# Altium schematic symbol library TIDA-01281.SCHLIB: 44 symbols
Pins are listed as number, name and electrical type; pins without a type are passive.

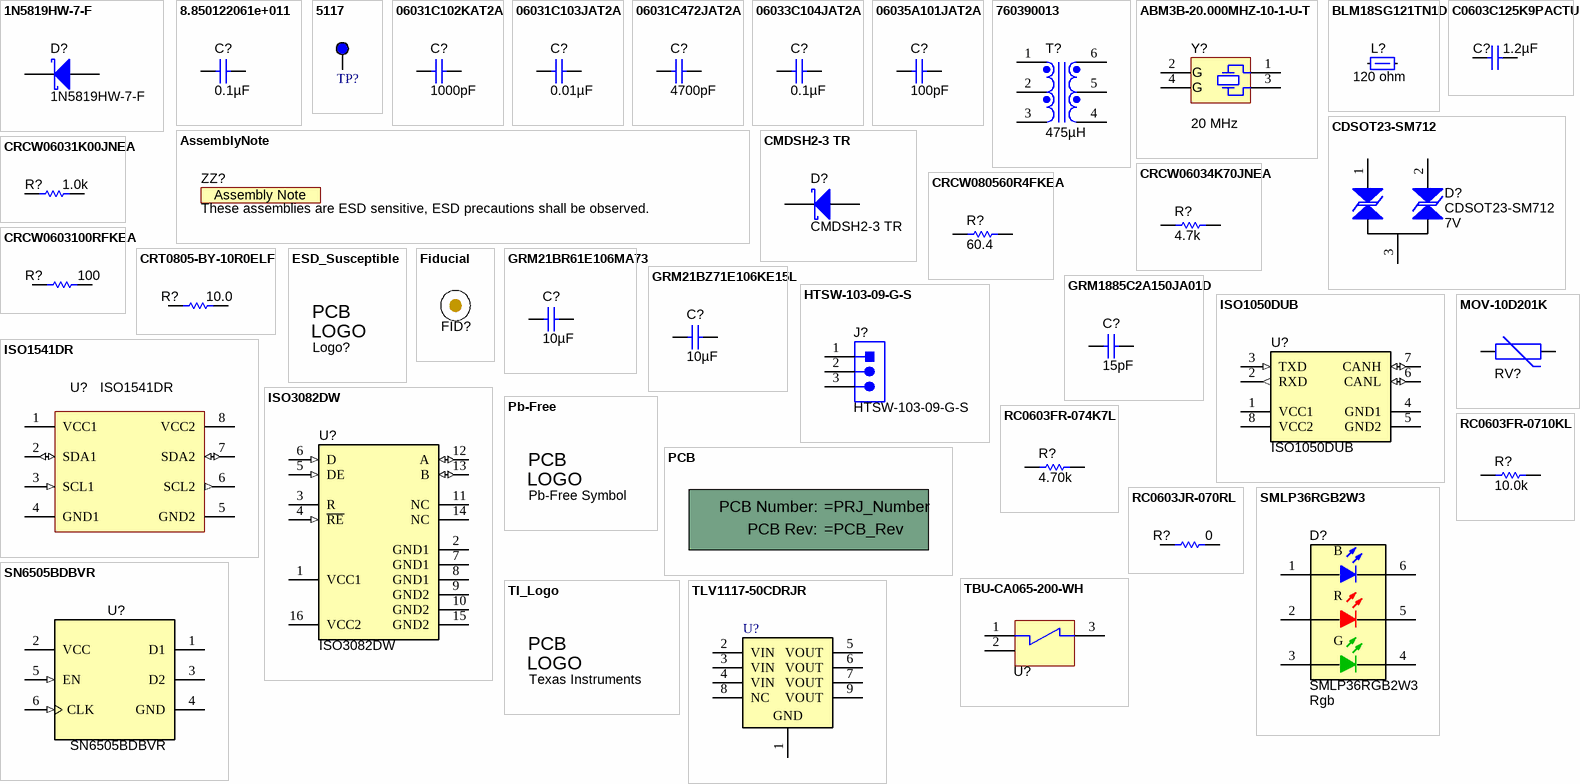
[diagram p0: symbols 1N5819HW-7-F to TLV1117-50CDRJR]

## 1N5819HW-7-F
designator D?
Diode, Schottky, 40 V, 1 A, SOD-123; Manufacturer: Diodes Inc.; U/M: EA; Vf_V: 0.45; Value: 40V; Value1: 1A; Value2: 0.45V; Io_A: 1; Vr_V: 40; TJmax_C: 125; SizeAreaWB_mm2: 13.095; SizeArea_mm2: 6.545; SizeX_mm: 3.85; SizeY_mm: 1.7; SizeZ_mm: 1.35; AEC Category: Q101
signal-integrity model Diode
simulation model DI_1N5819HW
footprint SOD-123
pins: 1 K, 2 A

## 8.850122061e+011
designator C?  ValueDisplayed: 0.1µF  (hidden comment: 8.850122061e+011)
CAP, CERM, 0.1 µF, 50 V, +/- 10%, X7R, 0603; Manufacturer: Wurth Elektronik; Polarized: N; CompType: Capacitor; Value: 0.1uF; U/M: EA; Cap_F: 0.0000001; Tolerance_%: 10; Value1: Unknown; VDC_V: 50; Value2: 50V; TaMin_C: -55; TaMax_C: 125; Cap_Case: 0603; SizeArea_mm2: 1.28; SizeAreaWB_mm2: 4.68; SizeX_mm: 1.6; SizeY_mm: 0.8; SizeZ_mm: 1; AEC Category: Q200
signal-integrity model Cap
simulation model Cap
footprint 0603
footprint 0603M
footprint 0603L
footprint 0603_HV
footprint 0603S
pins: 1, 2

## 5117
designator TP?  (value not drawn)
Test Point, Miniature, Blue, TH; Manufacturer: Keystone; CompType: Test Point Loop; U/M: EA; ContactFinish: Silver
footprint Keystone5117
pins: 1

## 06031C102KAT2A
designator C?  ValueDisplayed: 1000pF  (hidden comment: 06031C102KAT2A)
CAP, CERM, 1000 pF, 100 V, +/- 10%, X7R, 0603; Manufacturer: AVX; Polarized: N; CompType: Capacitor; Value: 1000pF; U/M: EA; Cap_F: 0.000000001; Tolerance_%: 10; ESR_ohm: 0.276; Value1: 0.276 ohm; VDC_V: 100; Value2: 100V; TaMin_C: -55; TaMax_C: 125; Cap_Case: 0603
signal-integrity model Cap
simulation model Cap
footprint 0603
footprint 0603M
footprint 0603L
footprint 0603_HV
footprint 0603S
pins: 1, 2

## 06031C103JAT2A
designator C?  ValueDisplayed: 0.01µF  (hidden comment: 06031C103JAT2A)
CAP, CERM, 0.01 µF, 100 V, +/- 5%, X7R, 0603; Manufacturer: AVX; Polarized: N; CompType: Capacitor; Value: 0.01uF; U/M: EA; Cap_F: 0.00000001; Tolerance_%: 5; ESR_ohm: 0.098; Value1: 0.098 ohm; VDC_V: 100; Value2: 100V; TaMin_C: -55; TaMax_C: 125; Cap_Case: 0603
signal-integrity model Cap
simulation model Cap
footprint 0603
footprint 0603M
footprint 0603L
footprint 0603_HV
footprint 0603S
pins: 1, 2

## 06031C472JAT2A
designator C?  ValueDisplayed: 4700pF  (hidden comment: 06031C472JAT2A)
CAP, CERM, 4700 pF, 100 V, +/- 5%, X7R, 0603; Manufacturer: AVX; Polarized: N; CompType: Capacitor; Value: 4700pF; U/M: EA; Cap_F: 0.0000000047; Tolerance_%: 5; ESR_ohm: 0.136; Value1: 0.136 ohm; VDC_V: 100; Value2: 100V; TaMin_C: -55; TaMax_C: 125; Cap_Case: 0603; SizeArea_mm2: 1.28; SizeAreaWB_mm2: 4.68; SizeX_mm: 1.6; SizeY_mm: 0.8; SizeZ_mm: 1; AEC Category: Q200
signal-integrity model Cap
simulation model Cap
footprint 0603
footprint 0603M
footprint 0603L
footprint 0603_HV
footprint 0603S
pins: 1, 2

## 06033C104JAT2A
designator C?  ValueDisplayed: 0.1µF  (hidden comment: 06033C104JAT2A)
CAP, CERM, 0.1 µF, 25 V, +/- 5%, X7R, 0603; Manufacturer: AVX; Polarized: N; CompType: Capacitor; Value: 0.1uF; U/M: EA; Cap_F: 0.0000001; Tolerance_%: 5; ESR_ohm: 0.05; Value1: 0.05 ohm; VDC_V: 25; Value2: 25V; TaMin_C: -55; TaMax_C: 125; Cap_Case: 0603
signal-integrity model Cap
simulation model Cap
footprint 0603
footprint 0603M
footprint 0603L
footprint 0603_HV
footprint 0603S
pins: 1, 2

## 06035A101JAT2A
designator C?  ValueDisplayed: 100pF  (hidden comment: 06035A101JAT2A)
CAP, CERM, 100 pF, 50 V, +/- 5%, C0G/NP0, 0603; Manufacturer: AVX; Polarized: N; CompType: Capacitor; Value: 100pF; U/M: EA; Cap_F: 0.0000000001; Tolerance_%: 5; ESR_ohm: 0.119; Value1: 0.119 ohm; VDC_V: 50; Value2: 50V; TaMin_C: -55; TaMax_C: 125; Cap_Case: 0603; SizeArea_mm2: 1.28; SizeAreaWB_mm2: 4.68; SizeX_mm: 1.6; SizeY_mm: 0.8; SizeZ_mm: 1; AEC Category: Q200
signal-integrity model Cap
simulation model Cap
footprint 0603
footprint 0603M
footprint 0603L
footprint 0603_HV
footprint 0603S
pins: 1, 2

## 760390013
designator T?  ValueDisplayed: 475µH  (hidden comment: 760390013)
Transformer, 475 uH, SMT; Manufacturer: Wurth Elektronik; SymbolCreator: a0799628; Value: 475uH; Lp: 475; DCR_ohm: 0.32
footprint Wurth_760390013
pins: 1, 2, 3, 4, 5, 6

## ABM3B-20.000MHZ-10-1-U-T
designator Y?  Frequency: 20 MHz  (hidden comment: ABM3B-20.000MHZ-10-1-U-T)
Crystal, 20 MHz, 10 pF, SMD; Manufacturer: Abracon Corportation; SymbolCreator: a0412235; U/M: EA; TaMin_C: -10; TaMax_C: 60; Frequency Stability: ±10ppm
footprint ABRACON_ABM3B
pins: 1, 2 GND (power), 3, 4 GND (power)

## AssemblyNote
designator ZZ?, comment These assemblies are ESD sensitive, ESD precautions shall be observed.  (no BOM)
SymbolCreator: codlsc; CompType: AssemblyNote
footprint AssemblyNote

## BLM18SG121TN1D
designator L?  value 120 ohm  (hidden comment: BLM18SG121TN1D)
Ferrite Bead, 120 ohm @ 100 MHz, 3 A, 0603; Manufacturer: MuRata; Imax_A: 3; DCR_ohm: 0.025; Value1: 0.025 ohm; Value2: 3A; ZTyp@100MHz_Ohm: 120
footprint 0603
footprint 0603M
footprint 0603L
footprint 0603_HV
footprint 0603S
pins: 1, 2

## C0603C125K9PACTU
designator C?  ValueDisplayed: 1.2µF  (hidden comment: C0603C125K9PACTU)
CAP, CERM, 1.2 µF, 6.3 V, +/- 10%, X5R, 0603; Manufacturer: Kemet; Polarized: N; CompType: Capacitor; Value: 1.2uF; U/M: EA; Cap_F: 0.0000012; Tolerance_%: 10; Value1: Unknown; VDC_V: 6.3; Value2: 6.3V; TaMin_C: -55; TaMax_C: 85; Cap_Case: 0603
signal-integrity model Cap
simulation model Cap
footprint 0603
footprint 0603M
footprint 0603L
footprint 0603_HV
footprint 0603S
pins: 1, 2

## CDSOT23-SM712
designator D?  value 7V
Diode, TVS, Bi, 7 V, 400 W, SOT-23; Manufacturer: Bourns; SymbolCreator: a0411947; U/M: EA; Power_W: 400; Vr_V: 7; Value1: 400W
footprint SOT-23
footprint SOT-23M
footprint SOT-23L
pins: 1, 2, 3

## CMDSH2-3 TR
designator D?
Diode, Schottky, 30 V, 0.2 A, SOD-323; Manufacturer: Central Semiconductor; U/M: EA; Vf_V: 0.55; Value: 30V; Value1: 0.2A; Value2: 0.55V; Io_A: 0.2; Vr_V: 30; TJmax_C: 150; SizeAreaWB_mm2: 8.695; SizeArea_mm2: 3.645; SizeX_mm: 2.7; SizeY_mm: 1.35; SizeZ_mm: 1; AEC Category: Q101
signal-integrity model Diode
footprint SOD-323
pins: 1 K, 2 A

## CRCW06031K00JNEA
designator R?  ValueDisplayed: 1.0k  (hidden comment: CRCW06031K00JNEA)
RES, 1.0 k, 5%, 0.1 W, 0603; Manufacturer: Vishay-Dale; CompType: Resistor; Value: 1.0k; Res_ohm: 1000; Value_Code: 1k00; Tolerance_%: 5; Power_W: 0.1; Value2: 0.1W; VDC_V: 75; TempCo: 200 ppm/C; EIA_Code: E24; U/M: EA
signal-integrity model Resistor
simulation model Resistor
footprint 0603
footprint 0603M
footprint 0603L
footprint 0603_HV
footprint 0603S
pins: 1, 2

## CRCW06034K70JNEA
designator R?  ValueDisplayed: 4.7k  (hidden comment: CRCW06034K70JNEA)
RES, 4.7 k, 5%, 0.1 W, 0603; Manufacturer: Vishay-Dale; CompType: Resistor; Value: 4.7k; Res_ohm: 4700; Value_Code: 4k70; Tolerance_%: 5; Power_W: 0.1; Value2: 0.1W; VDC_V: 75; TempCo: 200 ppm/C; SizeArea_mm2: 1.28; SizeX_mm: 1.6; SizeY_mm: 0.8; SizeZ_mm: 1; EIA_Code: E24; U/M: EA; AEC Category: Q200
signal-integrity model Resistor
simulation model Resistor
footprint 0603
footprint 0603M
footprint 0603L
footprint 0603_HV
footprint 0603S
pins: 1, 2

## CRCW080560R4FKEA
designator R?  ValueDisplayed: 60.4  (hidden comment: CRCW080560R4FKEA)
RES, 60.4, 1%, 0.125 W, 0805; Manufacturer: Vishay-Dale; CompType: Resistor; Value: 60.4; Value_Code: 60R4; Tolerance_%: 1; Power_W: 0.125; Value2: 0.125W; VDC_V: 150; TempCo: 100 ppm/C; EIA_Code: E96; U/M: EA; AEC Category: Q200
signal-integrity model Resistor
simulation model Resistor
footprint 0805_HV
footprint 0805_HV1
footprint 0805
footprint 0805M
pins: 1, 2

## CRCW0603100RFKEA
designator R?  ValueDisplayed: 100  (hidden comment: CRCW0603100RFKEA)
RES, 100, 1%, 0.1 W, 0603; Manufacturer: Vishay-Dale; CompType: Resistor; Value: 100; Value_Code: 100R; Tolerance_%: 1; Power_W: 0.1; Value2: 0.1W; VDC_V: 75; TempCo: 100 ppm/C; EIA_Code: E96; U/M: EA
signal-integrity model Resistor
simulation model Resistor
footprint 0603
footprint 0603M
footprint 0603L
footprint 0603_HV
footprint 0603S
pins: 1, 2

## CRT0805-BY-10R0ELF
designator R?  ValueDisplayed: 10.0  (hidden comment: CRT0805-BY-10R0ELF)
RES, 10.0, 0.1%, 0.1 W, 0805; Manufacturer: Bourns; CompType: Resistor; Value: 10.0; Res_ohm: 10; Value_Code: 10R0; Tolerance_%: 0.1; Value2: 0.1W; VDC_V: 100; TempCo: 25 ppm/C; EIA_Code: E192; U/M: EA
signal-integrity model Resistor
simulation model Resistor
footprint 0805_HV
footprint 0805_HV1
footprint 0805
footprint 0805M
pins: 1, 2

## ESD_Susceptible
designator Logo?, comment ESD Susceptible  (value not drawn)  (no BOM)
ESD Susceptible Symbol; SymbolCreator: a0412235
footprint ESD_Overlay_Large
footprint ESD_Overlay_Medium
footprint ESD_Overlay_Small

## Fiducial
designator FID?  (value not drawn)
Fiducial mark.  There is nothing to buy or mount.; SymbolCreator: codlsc
footprint Fiducial10-30
footprint Fiducial10-20
footprint Fiducial15-30
footprint Fiducial20-40
footprint Fiducial6.4-20

## GRM21BR61E106MA73
designator C?  ValueDisplayed: 10µF  (hidden comment: GRM21BR61E106MA73)
CAP, CERM, 10 µF, 25 V, +/- 20%, X5R, 0805; Manufacturer: MuRata; Polarized: N; CompType: Capacitor; Value: 10uF; U/M: EA; Cap_F: 0.00001; Tolerance_%: 20; Value1: Unknown; VDC_V: 25; Value2: 25V; TaMin_C: -55; TaMax_C: 85; Cap_Case: 0805; SizeArea_mm2: 2.5; SizeAreaWB_mm2: 6.75; SizeX_mm: 2; SizeY_mm: 1.25; SizeZ_mm: 1.45; AEC Category: Q200
signal-integrity model Cap
simulation model Cap
footprint 0805_HV
footprint 0805_HV1
footprint 0805
footprint 0805M
footprint 0805L
pins: 1, 2

## GRM21BZ71E106KE15L
designator C?  ValueDisplayed: 10µF  (hidden comment: GRM21BZ71E106KE15L)
CAP, CERM, 10 µF, 25 V, +/- 10%, X7R, 0805; Manufacturer: MuRata; Polarized: N; CompType: Capacitor; Value: 10uF; U/M: EA; Cap_F: 0.00001; Tolerance_%: 10; Value1: Unknown; VDC_V: 25; Value2: 25V; TaMin_C: -55; TaMax_C: 125; Cap_Case: 0805; SizeArea_mm2: 2.5; SizeAreaWB_mm2: 6.75; SizeX_mm: 2; SizeY_mm: 1.25; SizeZ_mm: 1.45; AEC Category: Q200
signal-integrity model Cap
simulation model Cap
footprint 0805_HV
footprint 0805_HV1
footprint 0805
footprint 0805M
footprint 0805L
pins: 1, 2

## GRM1885C2A150JA01D
designator C?  ValueDisplayed: 15pF  (hidden comment: GRM1885C2A150JA01D)
CAP, CERM, 15 pF, 100 V, +/- 5%, C0G/NP0, 0603; Manufacturer: MuRata; Polarized: N; CompType: Capacitor; Value: 15pF; U/M: EA; Cap_F: 0.000000000015; Tolerance_%: 5; Value1: Unknown; VDC_V: 100; Value2: 100V; TaMin_C: -55; TaMax_C: 125; Cap_Case: 0603
signal-integrity model Cap
simulation model Cap
footprint 0603
footprint 0603M
footprint 0603L
footprint 0603_HV
footprint 0603S
pins: 1, 2

## HTSW-103-09-G-S
designator J?
Header, 100mil, 3x1, Gold, TH; Manufacturer: Samtec; SymbolCreator: a0799628; Pitch_mm: 2.54; Gender: Male; Row_Count: 1; Cert_CSA: Y
footprint Samtec_HTSW-103-09-x-S
pins: 1, 2, 3
3 alternate drawings of the same symbol

## ISO1050DUB
designator U?
Isolated CAN Transceiver, -55 to 105 degC, 8-pin SOP (DUB), Green (RoHS & no Sb/Br); Manufacturer: Texas Instruments; Alternate PartNumber: Equivalent; Drivers Per Package: 1; Isolated: Yes; Rating: Catalog
footprint DUB0008A_N (SOP, 8-Leads, Body 9.5x6.62mm, Pitch 2.54mm, IPC Medium Density)
footprint DUB0008A_L (SOP, 8-Leads, Body 9.5x6.62mm, Pitch 2.54mm, IPC High Density)
footprint DUB0008A_M (SOP, 8-Leads, Body 9.5x6.62mm, Pitch 2.54mm, IPC Low Density)
pins: 1 VCC1 (power), 2 RXD (out), 3 TXD (in), 4 GND1 (power), 5 GND2 (power), 6 CANL (io), 7 CANH (io), 8 VCC2 (power)

## ISO1541DR
designator U?
Low-Power Bidirectional I2C Isolators, D0008A; Manufacturer: Texas Instruments; SymbolCreator: a0411947; CompType: IC; U/M: EA
footprint D0008A_N
footprint D0008A_M
footprint D0008A_L
pins: 1 VCC1 (power), 2 SDA1 (io), 3 SCL1 (in), 4 GND1 (power), 5 GND2 (power), 6 SCL2 (out), 7 SDA2 (io), 8 VCC2 (power)
1 alternate drawing of the same symbol

## ISO3082DW
designator U?
Isolated RS-485 Transceiver, 0.2 Mbps, 5 V, Half Duplex, -40 to 85 degC, 16-pin SOIC (DW), Green (RoHS & no Sb/Br); Manufacturer: Texas Instruments; Alternate PartNumber: Equivalent; # of TX/RX: 1 TX / 1 RX; Drivers Per Package: 1; Isolated: Yes; Number of Nodes: 256; Signaling Rate(Mbps): 0.2; Common Mode Range: -7 to 12; ESD(kV): 16; Fault Protection(V): -9 to 14; Fail Safe: Idle, Open, Short; ICC(Max)(mA): 15; Supply Voltage(s)(V): 5; Rating: Catalog
footprint DW0016A_N (SOIC, 16-Leads, Body 10.3x7.5mm, Pitch 1.27mm, IPC Medium Density)
footprint DW0016A_L (SOIC, 16-Leads, Body 10.3x7.5mm, Pitch 1.27mm, IPC High Density)
footprint DW0016A_M (SOIC, 16-Leads, Body 10.3x7.5mm, Pitch 1.27mm, IPC Low Density)
pins: 1 VCC1 (power), 2 GND1 (power), 3 R (hiz), 4 ~{RE} (in), 5 DE (in), 6 D (in), 7 GND1 (power), 8 GND1 (power), 9 GND2 (power), 10 GND2 (power), 11 NC, 12 A (io), 13 B (io), 14 NC, 15 GND2 (power), 16 VCC2 (power)

## MOV-10D201K
designator RV?  (value not drawn)
Metal Oxide Varistor, TH; Manufacturer: Bourns; SymbolCreator: a0412235; Value: 200V
footprint Bourns_MOV-10DxxxK
pins: 1, 2

## Pb-Free
designator Logo?, comment Pb-Free Symbol  (no BOM)
SymbolCreator: a0412235
footprint Pb-Free_Overlay_Medium
footprint Pb-Free_Overlay_Small

## PCB
designator !PCB?, comment Printed Circuit Board  (value not drawn)  (mechanical)
Manufacturer: Any; SymbolCreator: a0412235; CompType: PCB
1 alternate drawing of the same symbol

## RC0603FR-074K7L
designator R?  ValueDisplayed: 4.70k  (hidden comment: RC0603FR-074K7L)
RES, 4.70 k, 1%, 0.1 W, 0603; Manufacturer: Yageo America; CompType: Resistor; Value: 4.70k; Res_ohm: 4700; Value_Code: 4k70; Tolerance_%: 1; Power_W: 0.1; Value2: 0.1W; VDC_V: 150; TempCo: 200 ppm/C; U/M: EA
signal-integrity model Resistor
simulation model Resistor
footprint 0603
footprint 0603M
footprint 0603L
footprint 0603_HV
footprint 0603S
pins: 1, 2

## RC0603FR-0710KL
designator R?  ValueDisplayed: 10.0k  (hidden comment: RC0603FR-0710KL)
RES, 10.0 k, 1%, 0.1 W, 0603; Manufacturer: Yageo America; CompType: Resistor; Value: 10.0k; Res_ohm: 10000; Value_Code: 10k0; Tolerance_%: 1; Power_W: 0.1; Value2: 0.1W; VDC_V: 150; TempCo: 200 ppm/C; EIA_Code: E96; U/M: EA
signal-integrity model Resistor
simulation model Resistor
footprint 0603
footprint 0603M
footprint 0603L
footprint 0603_HV
footprint 0603S
pins: 1, 2

## RC0603JR-070RL
designator R?  ValueDisplayed: 0  (hidden comment: RC0603JR-070RL)
RES, 0, 5%, 0.1 W, 0603; Manufacturer: Yageo America; CompType: Resistor; Value: 0; Value_Code: 0000; Tolerance_%: 5; Power_W: 0.1; Value2: 0.1W; VDC_V: 50; TempCo: 200 ppm/C; EIA_Code: E24; U/M: EA
signal-integrity model Resistor
simulation model Resistor
footprint 0603
footprint 0603M
footprint 0603L
footprint 0603_HV
footprint 0603S
pins: 1, 2

## SMLP36RGB2W3
designator D?  value Rgb
LED, Rgb, SMD; Manufacturer: Rohm; SymbolCreator: Altium; Vf_V: 3.1; Value2: 3.1V; Io_A: 0.005; Vr_V: 5; Ir_A: 1e-005; Tjmax_C: 85; Value1: W; U/M: EA
footprint PicoLED_RGB_150x100
pins: 1 A, 2, 3, 4, 5, 6

## SN6505BDBVR
designator U?
LOW-NOISE 1A TRANSFORMER DRIVERS FOR ISOLATED POWER SUPPLIES, DBV0006A; Alternate PartNumber: SN6505BDBVT; Manufacturer: Texas Instruments; SymbolCreator: Altium; SizeArea_mm2: 8.12; SizeAreaWB_mm2: 14.82; SizeX_mm: 2.8; SizeY_mm: 2.9; SizeZ_mm: 1.45; CompType: IC; U/M: EA
footprint DBV0006A_N
footprint DBV0006A_M
footprint DBV0006A_L
pins: 1 D1 (oc), 2 VCC (power), 3 D2 (oc), 4 GND (power), 5 EN (in), 6 CLK (in)
1 alternate drawing of the same symbol

## TBU-CA065-200-WH
designator U?  (value not drawn)
TBU-CA series TBU High-Speed Protectors, TBU-CA; Manufacturer: Bourns; SymbolCreator: x0208325
footprint TBU-CA
pins: 1 Line In/Out, 2 NU, 3 Line Out/In

## TI_Logo
designator Logo?, comment Texas Instruments  (no BOM)
Texas Instrument Corporate Signature; SymbolCreator: codlsc
footprint TI_Stacked_SolderMask_Medium
footprint TI_Stacked_SolderMask_Small
footprint TI_Stacked_Overlay_Medium
footprint TI_Stacked_Overlay_Small
footprint TI_Horizontal_SolderMask_Medium
footprint TI_Horizontal_SolderMask_Small
footprint TI_Horizontal_Overlay_Medium
footprint TI_Horizontal_Overlay_Small
footprint TI_Symbol_SolderMask_Small
footprint TI_Symbol_Overlay_Medium
footprint TI_Symbol_Overlay_Small
footprint TI_Symbol_SolderMask_Medium

## TLV1117-50CDRJR
designator U?  (value not drawn)
LDO with 6.4 to 15 V Input and 5 V Output, 0 to 125 degC, 8-Pin SON (DRJ), Green (RoHS & no Sb/Br); Manufacturer: Texas Instruments; Alternate PartNumber: Equivalent; Iout(Max)(A): 0.8; Iq(Typ)(mA): 5; Vdo(Typ)(V): 1.2; Vin(Max)(V): 15; Vin(Min)(V): 6.4
footprint DRJ0008A (SON, 8-Leads, Body 4x4mm, Pitch 0.8mm, Thermal Pad 3x2.2mm, TI Recommended)
pins: 1 ADJ/GND (power), 2 VIN (power), 3 VIN (power), 4 VIN (power), 5 VOUT (power), 6 VOUT (power), 7 VOUT (power), 8 NC, 9 VOUT (power)

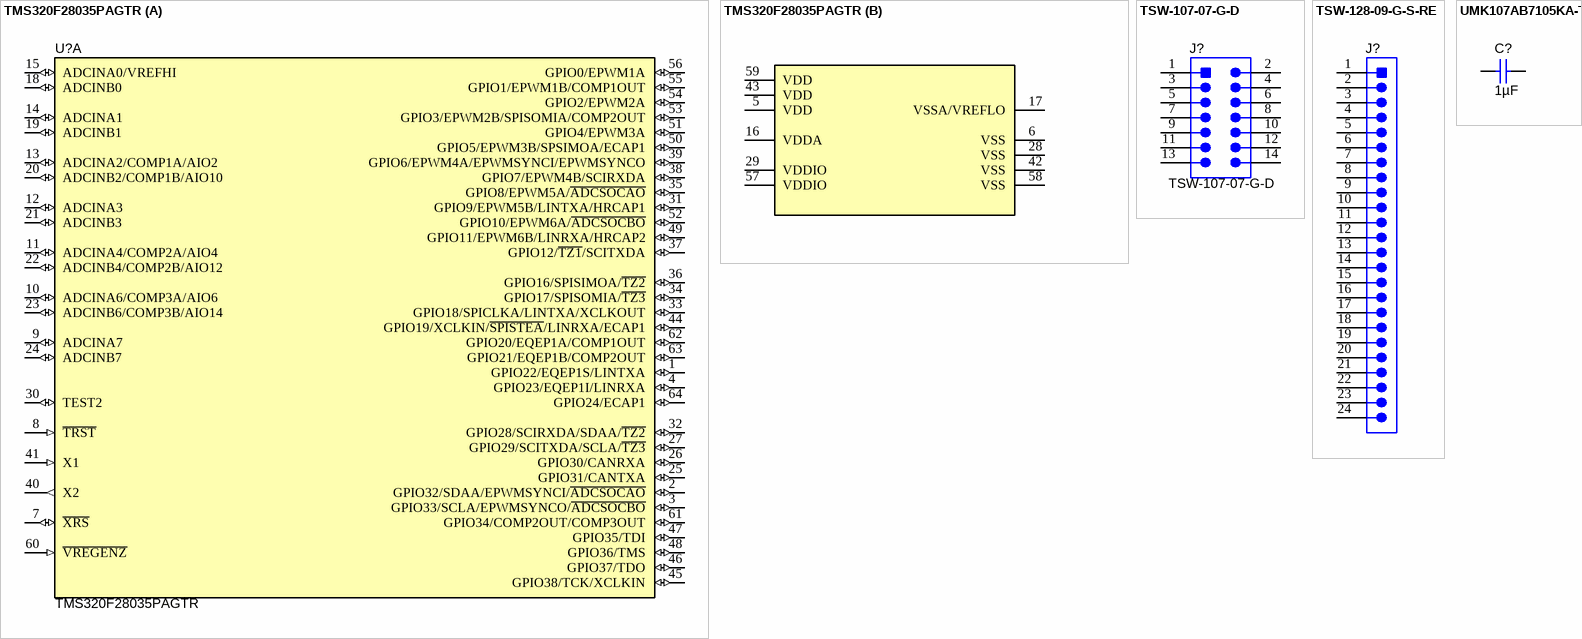
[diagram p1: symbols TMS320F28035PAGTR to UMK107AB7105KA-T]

## TMS320F28035PAGTR
designator U?
Piccolo(TM) Microcontrollers, PAG0064A; Manufacturer: Texas Instruments; SymbolCreator: a0412235; SizeArea_mm2: 144; SizeAreaWB_mm2: 196; SizeX_mm: 12; SizeZ_mm: 1.2; CompType: IC; U/M: EA
footprint PAG0064A_N
footprint PAG0064A_M
footprint PAG0064A_L
part A pins: 1 GPIO22/EQEP1S/LINTXA (io), 2 GPIO32/SDAA/EPWMSYNCI/~{ADCSOCAO} (io), 3 GPIO33/SCLA/EPWMSYNCO/~{ADCSOCBO} (io), 4 GPIO23/EQEP1I/LINRXA (io), 7 ~{XRS} (io), 8 ~{TRST} (in), 9 ADCINA7 (io), 10 ADCINA6/COMP3A/AIO6 (io), 11 ADCINA4/COMP2A/AIO4 (io), 12 ADCINA3 (io), 13 ADCINA2/COMP1A/AIO2 (io), 14 ADCINA1 (io), 15 ADCINA0/VREFHI (io), 18 ADCINB0 (io), 19 ADCINB1 (io), 20 ADCINB2/COMP1B/AIO10 (io), 21 ADCINB3 (io), 22 ADCINB4/COMP2B/AIO12 (io), 23 ADCINB6/COMP3B/AIO14 (io), 24 ADCINB7 (io), 25 GPIO31/CANTXA (io), 26 GPIO30/CANRXA (io), 27 GPIO29/SCITXDA/SCLA/~{TZ3} (io), 30 TEST2 (io), 31 GPIO9/EPWM5B/LINTXA/HRCAP1 (io), 32 GPIO28/SCIRXDA/SDAA/~{TZ2} (io), 33 GPIO18/SPICLKA/LINTXA/XCLKOUT (io), 34 GPIO17/SPISOMIA/~{TZ3} (io), 35 GPIO8/EPWM5A/~{ADCSOCAO} (io), 36 GPIO16/SPISIMOA/~{TZ2} (io), 37 GPIO12/~{TZ1}/SCITXDA (io), 38 GPIO7/EPWM4B/SCIRXDA (io), 39 GPIO6/EPWM4A/EPWMSYNCI/EPWMSYNCO (io), 40 X2 (out), 41 X1 (in), 44 GPIO19/XCLKIN/~{SPISTEA}/LINRXA/ECAP1 (io), 45 GPIO38/TCK/XCLKIN (io), 46 GPIO37/TDO (io), 47 GPIO35/TDI (io), 48 GPIO36/TMS (io), 49 GPIO11/EPWM6B/LINRXA/HRCAP2 (io), 50 GPIO5/EPWM3B/SPSIMOA/ECAP1 (io), 51 GPIO4/EPWM3A (io), 52 GPIO10/EPWM6A/~{ADCSOCBO} (io), 53 GPIO3/EPWM2B/SPISOMIA/COMP2OUT (io), 54 GPIO2/EPWM2A (io), 55 GPIO1/EPWM1B/COMP1OUT (io), 56 GPIO0/EPWM1A (io), 60 ~{VREGENZ} (in), 61 GPIO34/COMP2OUT/COMP3OUT (io), 62 GPIO20/EQEP1A/COMP1OUT (io), 63 GPIO21/EQEP1B/COMP2OUT (io), 64 GPIO24/ECAP1 (io)
part B pins: 5 VDD (power), 6 VSS (power), 16 VDDA (power), 17 VSSA/VREFLO (power), 28 VSS (power), 29 VDDIO (power), 42 VSS (power), 43 VDD (power), 57 VDDIO (power), 58 VSS (power), 59 VDD (power)
1 alternate drawing of the same symbol

## TSW-107-07-G-D
designator J?
Header, 100mil, 7x2, Gold, TH; Manufacturer: Samtec; SymbolCreator: a0412235; Pitch_mm: 2.54; Gender: Male; Shrouded: N; Row_Count: 2; Current_A: 6.3; Voltage_V: 550; Cert_CSA: Y
footprint TSW-107-07-G-D
footprint TSW-107-07-X-D
pins: 1, 2, 3, 4, 5, 6, 7, 8, 9, 10, 11, 12, 13, 14

## TSW-128-09-G-S-RE
designator J?  (value not drawn)
Header, 100mil, 28x1, Gold, R/A, TH; Manufacturer: Samtec; SymbolCreator: a0412235; Pitch_mm: 2.54; Gender: Male; Shrouded: N; Row_Count: 1; Current_A: 6.3; Voltage_V: 550; Cert_CSA: Y
footprint CONN_TSW-128-09-X-S-RE
pins: 1, 2, 3, 4, 5, 6, 7, 8, 9, 10, 11, 12, 13, 14, 15, 16, 17, 18, 19, 20, 21, 22, 23, 24

## UMK107AB7105KA-T
designator C?  ValueDisplayed: 1µF  (hidden comment: UMK107AB7105KA-T)
CAP, CERM, 1 µF, 50 V, +/- 10%, X7R, 0603; Manufacturer: Taiyo Yuden; Polarized: N; CompType: Capacitor; Value: 1uF; U/M: EA; Cap_F: 0.000001; Tolerance_%: 10; Value1: Unknown; VDC_V: 50; Value2: 50V; TaMin_C: -55; TaMax_C: 125; Cap_Case: 0603
signal-integrity model Cap
simulation model Cap
footprint 0603
footprint 0603M
footprint 0603L
footprint 0603_HV
footprint 0603S
pins: 1, 2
